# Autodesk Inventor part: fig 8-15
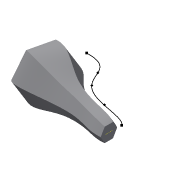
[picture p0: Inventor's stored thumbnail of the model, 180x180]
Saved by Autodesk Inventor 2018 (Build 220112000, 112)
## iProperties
Created: 2004-05
Part Number: fig 8-15
Document SubType Name: Modeling
Designer: CADCIM Technologies
Manufacturer: Standard
Standards Organization: Custom
Density: 1 g/cm^3
Material: Generic
Appearance: Default
Author: CADCIM Technologies
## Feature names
1. Sweep7
## Parameters: d6 = 0, d7 = 0
